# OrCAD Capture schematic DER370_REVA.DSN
size C
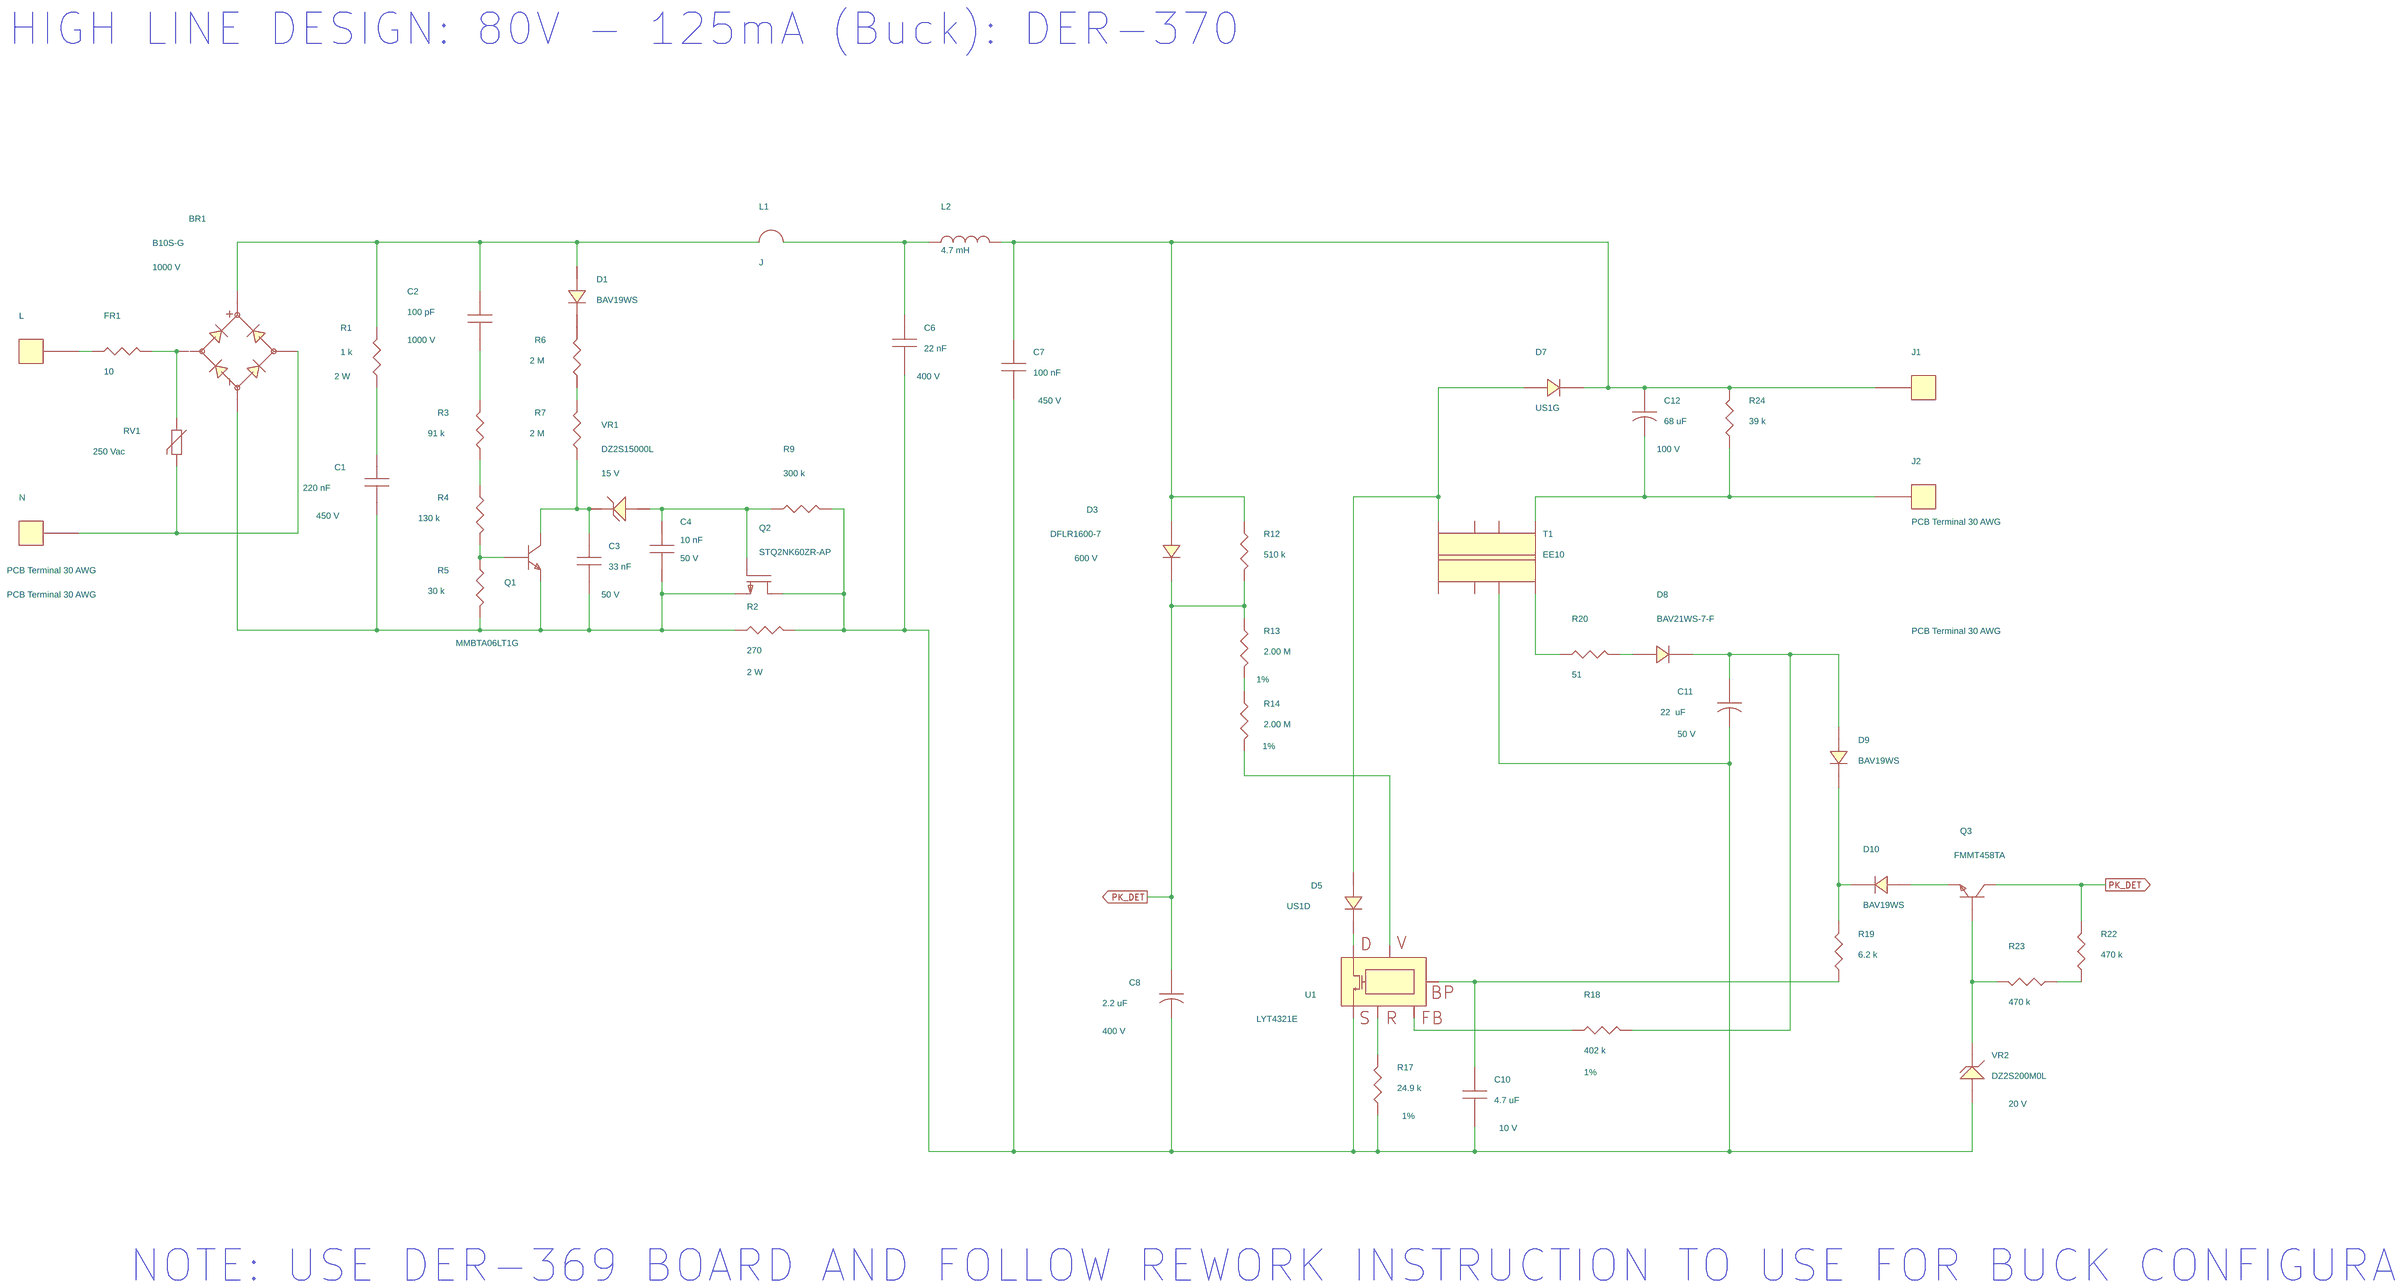
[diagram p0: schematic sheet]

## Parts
BR1  B10S-G  [pismsoic4]
C1  220 nF  [pi_np_cap_rad470x220ls400d40]
C2  100 pF  [pismc0805]
C3  33 nF  [pismc0805]
C4  10 nF  [pismc0603]
C6  22 nF  [pinpcaprad440x200300040]
C7  100 nF  [pinpcaprad440x200300040]
C8  2.2 uF  [pipolcapcyld250ls100030]
C10  4.7 uF  [pismc0805]
C11  22  uF  [pipolcapclyd200ls80030]
C12  68 uF  [pipolcapcyld400ls200040]
D1  BAV19WS  [pismsod323]
D3  DFLR1600-7  [pismddflr120012]
D5  US1D  [pismdsma]
D7  US1G  [pismdsma]
D8  BAV21WS-7-F  [pismsod323]
D9  BAV19WS  [pismsod323]
D10  BAV19WS  [pismsod323]
FR1  10  [pi12wvresd180ls200d040]
J1  PCB Terminal 30 AWG  [pi_hole_30awg]
J2  PCB Terminal 30 AWG  [pi_hole_30awg]
L  PCB Terminal 30 AWG  [pi_hole_30awg]
L1  J  [pi_jumper200]
L2  4.7 mH  [pi12wresd180ls675d040]
N  PCB Terminal 30 AWG  [pi_hole_30awg]
Q1  MMBTA06LT1G  [pismsot23132]
Q2  STQ2NK60ZR-AP  [PIT092100]
Q3  FMMT458TA  [pismsot23132]
R1  1 k  [pi12wresd180ls675d040]
R2  270  [pi2wvresd180ls200040]
R3  91 k  [pismr1206]
R4  130 k  [pismr1206]
R5  30 k  [pismr0603]
R6  2 M  [pismr0805]
R7  2 M  [pismr0805]
R9  300 k  [pismr0603]
R12  510 k  [pismr0805]
R13  2.00 M  [pismr1206]
R14  2.00 M  [pismr1206]
R17  24.9 k  [pismr0603]
R18  402 k  [pismr0603]
R19  6.2 k  [pismr0603]
R20  51  [pismr0805]
R22  470 k  [pismr0805]
R23  470 k  [pismr0805]
R24  39 k  [pismr0805]
RV1  250 Vac  [pidisc350x160ls210x140040]
T1  EE10  [pi_bobbin_ee10_8p]
U1  LYT4321E  [piicesip76th]
VR1  DZ2S15000L  [pi_sm_d_ssmini2p]
VR2  DZ2S200M0L  [pi_sm_d_ssmini2p]

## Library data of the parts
BR1 = DIODE_BRIDGE_~~+-: Disp_Voltage: 1000 V; Part Number: 15-00818-00
C1 = CAP_NP: Disp_Voltage: 450 V; Part Number: 20-08691-00; ROOM: 1; Voltage: 450 V
C2 = CAP_NP: Disp_Voltage: 1000 V; Part Number: 20-08675-00; Voltage: 1000 V
C3 = CAP_NP: Disp_Voltage: 50 V; Part Number: 20-01024 -00; Voltage: 50 V
C4 = CAP_NP: Disp_Voltage: 50 V; Part Number: 20-01051-00; Voltage: 50V
C6 = CAP_NP: Disp_Voltage: 400 V; Part Number: 20-00363-00; ROOM: 1; Voltage: 400 V
C7 = CAP_NP: Disp_Voltage: 450 V; Part Number: 20-08690-00; Voltage: 450 V
C8 = CAP_POL: ALT_SYMBOLS: pipolcapcyld250ls100030h; Disp_Voltage: 400 V; Part Number: 20-01008-00; Voltage: 400 V
C10 = CAP_NP: Disp_Voltage: 10 V; Part Number: 20-00612-00; Voltage: 10 V
C11 = CAP_POL: Disp_Voltage: 50 V; Part Number: 20-00950-00; Voltage: 50 V
C12 = CAP_POL: Disp_Voltage: 100 V; Part Number: 20-08688-00; Voltage: 100 V
D1 D9 D10 = DIODE: Part Number: 15-00658-00
D3 = DIODE: Disp_Voltage: 600 V; Part Number: 15-00826-00
D5 = DIODE: Part Number: 15-00492-00
D7 = DIODE: Part Number: 15-00493-00
D8 = DIODE: Part Number: 15-00385-00
FR1 = R: FPLIST: pi12wvresd180ls200d040,pi12wvresd180ls250d040,pi12wresd180ls675d040; Part Number: 05-03530-00
J1 J2 L N = TERM_1Pin: Part Number: 35-00026-00
L1 = JUMPER_1: Part Number: 65-00001-00
L2 = INDUCTOR: FPLIST: pi12wresd180ls675d040,pi12wvresd180ls150d040,pi12wvresd180ls200d040,pi12wvresd180ls250d040; Part Number: 30-00126-00
Q1 = NPN_BEC: Part Number: 55-00072-00
Q2 = FET_N_GDS: FPLIST: PITO92R100,PIT092100; Part Number: 50-00116-00
Q3 = NPN_BEC: Part Number: 55-00086-00
R1 = R: ALT_SYMBOLS: pi2wvresd180ls250040,pi12wresd180ls675d040; Disp_Power: 2 W; FPLIST: pi2wvresd180ls200040,pi2wvresd180ls250040,pi12wresd180ls675d040; Part Number: 05-05439-00; ROOM: 1
R2 = R: ALT_SYMBOLS: pi2wvresd180ls250040,pi12wresd180ls675d040; Disp_Power: 2 W; FPLIST: pi2wvresd180ls200040,pi2wvresd180ls250040,pi12wresd180ls675d040; Part Number: 05-05438-00
R3 = R: Part Number: 05-01399-00
R4 = R: Part Number: 05-01403-00
R5 = R: Part Number: 05-01723-00
R6 R7 = R: Part Number: 05-01598-00
R9 = R: Part Number: 05-01747-00
R12 = R: Part Number: 05-01584-00
R13 R14 = R: Disp_Tol: 1%; Part Number: 05-03156-00
R17 = R: Disp_Tol: 1%; Part Number: 05-03222-00
R18 = R: Disp_Tol: 1%; Part Number: 05-01232-00
R19 = R: Part Number: 05-01707-00
R20 = R: Part Number: 05-01488-00
R22 R23 = R: Part Number: 05-01583-00
R24 = R: Part Number: 05-01557-00
RV1 = VARISTOR: Part Number: 85-00033-00
T1 = BEE16_8P_GENERIC: Part Number: 25-00877-00
U1 = LNK40X_eSIP: Part Number: 10-00638-00
VR1 = DIODE_ZENER: Disp_Voltage: 15 V; Part Number: 15-00924-00
VR2 = DIODE_ZENER: Disp_Voltage: 20 V; Part Number: 15-01012-00

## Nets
PK_DET: C8.1 D3.1 Q3.3(COLLECTOR) R12.2 R13.1 R22.2
N2040939: C6.2 C7.2 C8.2 C10.2 C11.2 Q2.2(D) R2.2 R9.2 R17.1 T1.7 U1.5(S) VR2.2
N2229506: BR1.4 C1.2 C3.2 C4.2 Q1.2(EMITTER) Q2.3(S) R2.1 R5.2
N2232323: BR1.1 N.1 RV1.2
N2487375: BR1.2 FR1.2 RV1.1
N2491459: C10.1 R19.2 U1.4(BP)
N2492720: D5.1 U1.7(D)
N2492766: R17.2 U1.1(R)
N2493445: C12.2 J2.1 R24.2 T1.1
N2532048: R18.1 U1.3(FB)
N2538393: BR1.3 C2.1 D1.2 L1.2 R1.2
N2541951: R14.2 U1.2(V)
N2543404: C7.1 C12.1 D3.2 D7.1 J1.1 L2.1 R12.1 R24.1
N3718814: C11.1 D8.1 D9.2 R18.2
N3765694: D9.1 D10.1 R19.1
N3776097: C6.1 L1.1 L2.2
N3815881: FR1.1 L.1
N3840471: R13.2 R14.1
N3915236: C4.1 Q2.1(G) R9.1 VR1.2
N3915298: R3.2 R4.1
N3915302: C3.1 Q1.3(COLLECTOR) R7.1 VR1.1
N3915322: Q1.1(BASE) R4.2 R5.1
N3915464: C2.2 R3.1
N3918720: C1.1 R1.1
N3927142: Q3.1(BASE) R23.2 VR2.1
N3927314: D10.2 Q3.2(EMITTER)
N3985304: R20.1 T1.8
N4004994: D5.2 D7.2 T1.4
N4015758: R22.1 R23.1
N4024101: R6.1 R7.2
N4030121: D8.2 R20.2
N4060686: D1.1 R6.2

Not connected (* = marked no-connect by the designer): T1 2 3 5 6

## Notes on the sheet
- HIGH LINE DESIGN: 80V - 125mA (Buck): DER-370
- NOTE: USE DER-369 BOARD AND FOLLOW REWORK INSTRUCTION TO USE FOR BUCK CONFIGURATION
